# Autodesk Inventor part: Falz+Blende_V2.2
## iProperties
Created: 2008-06
Part Number: Falz+Blende_V2.2
Document SubType Name: Blech
Designer: Dirk
Density: 1 g/cm^3
Author: Dirk
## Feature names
1. Grobblech1
2. Grobblech8
3. Biegung7
